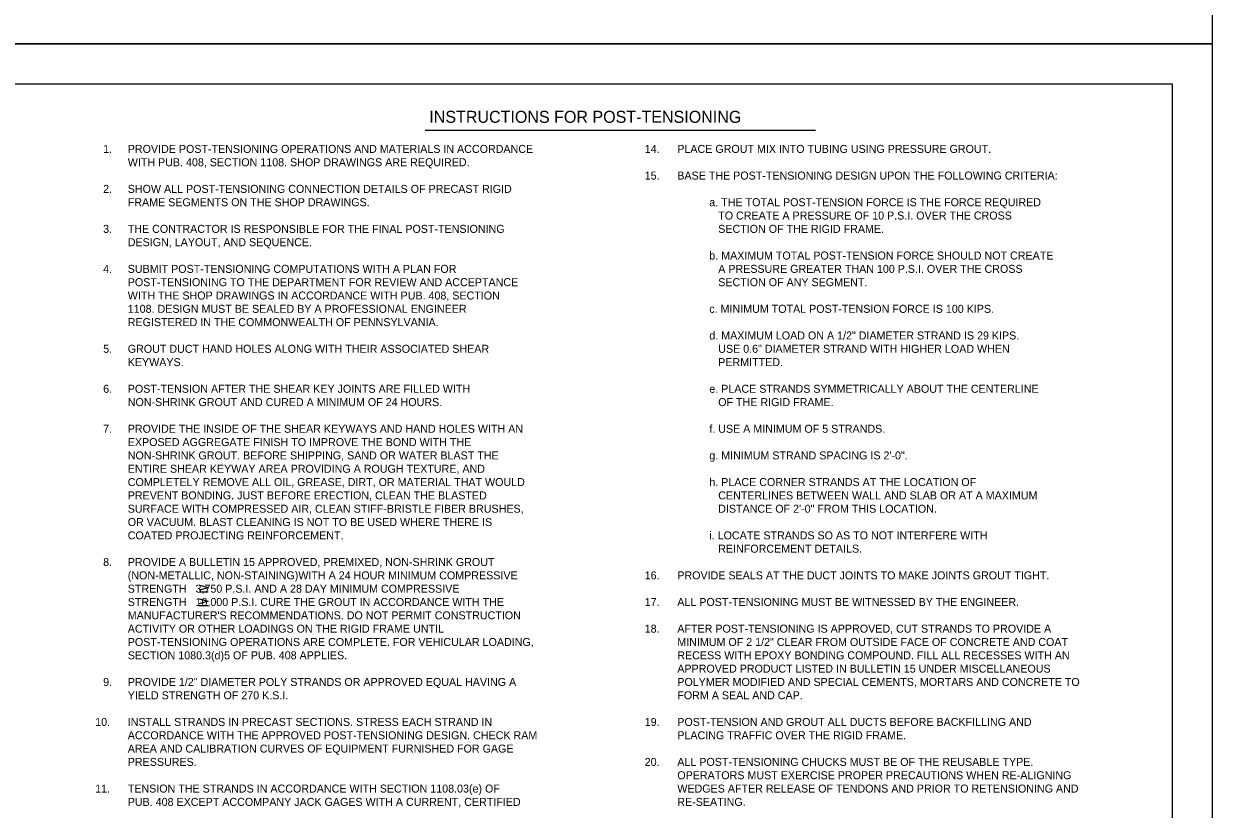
# Model space of a CAD drawing. Extents: x 641328 to 643024, y 298283 to 300065.
# Drawn here: x 642563.8 to 643009.5, y 299184.1 to 299478.8 of the extents above; entities that cross this region are included whole.
import ezdxf

# ---------------------------------------------------------------- set-up
doc = ezdxf.new("R2010")
doc.units = 0
doc.layers.add('2', color=7, linetype='Continuous')
doc.layers.add('PLT-BNDY', color=7, linetype='Continuous')

msp = doc.modelspace()

# ---------------------------------------------------------------- linework, layer by layer
at = {"layer": '2'}
for p, q in [((642208.51, 299456.3), (642994.5, 299456.3)), ((642994.5, 299456.3), (642994.5, 298892.3)), ((642714.31, 299438.86), (642860.76, 299438.86)), ((642629.74, 299268.18), (642633.11, 299267.31)), ((642629.6, 299265.61), (642632.97, 299265.61)), ((642629.74, 299266.43), (642633.11, 299267.31)), ((642629.44, 299260.5), (642632.82, 299260.5)), ((642629.58, 299263.07), (642632.96, 299262.2)), ((642629.58, 299261.32), (642632.96, 299262.2))]:
    msp.add_line(p, q, dxfattribs=at)
at = {"layer": 'PLT-BNDY'}
for points in [[(642168.51, 300065.3), (643009.51, 300065.3), (643009.51, 299471.3), (642168.51, 299471.3)], [(642168.51, 299471.3), (643009.51, 299471.3), (643009.51, 298877.3), (642168.51, 298877.3)]]:
    msp.add_lwpolyline(points, close=True, dxfattribs=at)

# ---------------------------------------------------------------- texts
at = {"layer": '2'}
for s, height, p in [('INSTRUCTIONS FOR POST-TENSIONING', 4.5, (642715.91, 299441.63)), ('1.', 3, (642593.61, 299430.34)), ('PROVIDE POST-TENSIONING OPERATIONS AND MATERIALS IN ACCORDANCE ', 3, (642602.83, 299430.34)), ('14.', 3, (642796.69, 299430.34)), ('PLACE GROUT MIX INTO TUBING USING PRESSURE GROUT. ', 3, (642808.91, 299430.34)), ('WITH PUB. 408, SECTION 1108. SHOP DRAWINGS ARE REQUIRED.', 3, (642602.83, 299425.34)), ('15.', 3, (642796.69, 299420.34)), ('BASE THE POST-TENSIONING DESIGN UPON THE FOLLOWING CRITERIA:', 3, (642808.91, 299420.34)), ('2.', 3, (642593.61, 299415.34)), ('SHOW ALL POST-TENSIONING CONNECTION DETAILS OF PRECAST RIGID ', 3, (642602.83, 299415.34)), ('FRAME SEGMENTS ON THE SHOP DRAWINGS.  ', 3, (642602.83, 299410.34)), ('a. THE TOTAL POST-TENSION FORCE IS THE FORCE REQUIRED ', 3, (642820.91, 299410.34)), ('   TO CREATE A PRESSURE OF 10 P.S.I. OVER THE CROSS ', 3, (642820.91, 299405.34)), ('3.', 3, (642593.61, 299400.34)), ('THE CONTRACTOR IS RESPONSIBLE FOR THE FINAL POST-TENSIONING ', 3, (642602.83, 299400.34)), ('   SECTION OF THE RIGID FRAME. ', 3, (642820.91, 299400.34)), ('DESIGN, LAYOUT, AND SEQUENCE.  ', 3, (642602.83, 299395.34)), ('b. MAXIMUM TOTAL POST-TENSION FORCE SHOULD NOT CREATE', 3, (642820.91, 299390.34)), ('4.', 3, (642593.61, 299385.34)), ('SUBMIT POST-TENSIONING COMPUTATIONS WITH A PLAN FOR ', 3, (642602.83, 299385.34)), ('   A PRESSURE GREATER THAN 100 P.S.I. OVER THE CROSS ', 3, (642820.91, 299385.34)), ('POST-TENSIONING TO THE DEPARTMENT FOR REVIEW AND ACCEPTANCE ', 3, (642602.83, 299380.34)), ('   SECTION OF ANY SEGMENT. ', 3, (642820.91, 299380.34)), ('WITH THE SHOP DRAWINGS IN ACCORDANCE WITH PUB. 408, SECTION ', 3, (642602.83, 299375.34)), ('1108. DESIGN MUST BE SEALED BY A PROFESSIONAL ENGINEER ', 3, (642602.83, 299370.34)), ('c. MINIMUM TOTAL POST-TENSION FORCE IS 100 KIPS.', 3, (642820.91, 299370.34)), ('REGISTERED IN THE COMMONWEALTH OF PENNSYLVANIA.', 3, (642602.83, 299365.34)), ('d. MAXIMUM LOAD ON A 1/2" DIAMETER STRAND IS 29 KIPS.', 3, (642820.91, 299360.34)), ('5.', 3, (642593.61, 299355.34)), ('GROUT DUCT HAND HOLES ALONG WITH THEIR ASSOCIATED SHEAR ', 3, (642602.83, 299355.34)), ('   USE 0.6" DIAMETER STRAND WITH HIGHER LOAD WHEN ', 3, (642820.91, 299355.34)), ('KEYWAYS.', 3, (642602.83, 299350.34)), ('   PERMITTED. ', 3, (642820.91, 299350.34)), ('6.', 3, (642593.61, 299340.34)), ('POST-TENSION AFTER THE SHEAR KEY JOINTS ARE FILLED WITH ', 3, (642602.83, 299340.34)), ('e. PLACE STRANDS SYMMETRICALLY ABOUT THE CENTERLINE ', 3, (642820.91, 299340.34)), ('NON-SHRINK GROUT AND CURED A MINIMUM OF 24 HOURS.', 3, (642602.83, 299335.34)), ('   OF THE RIGID FRAME.', 3, (642820.91, 299335.34)), ('7.', 3, (642593.61, 299325.34)), ('PROVIDE THE INSIDE OF THE SHEAR KEYWAYS AND HAND HOLES WITH AN ', 3, (642602.83, 299325.34)), ('f. USE A MINIMUM OF 5 STRANDS.', 3, (642820.91, 299325.34)), ('EXPOSED AGGREGATE FINISH TO IMPROVE THE BOND WITH THE ', 3, (642602.83, 299320.34)), ('NON-SHRINK GROUT. BEFORE SHIPPING, SAND OR WATER BLAST THE ', 3, (642602.83, 299315.34)), ('g. MINIMUM STRAND SPACING IS 2\'-0".', 3, (642820.91, 299315.34)), ('ENTIRE SHEAR KEYWAY AREA PROVIDING A ROUGH TEXTURE, AND ', 3, (642602.83, 299310.34)), ('COMPLETELY REMOVE ALL OIL, GREASE, DIRT, OR MATERIAL THAT WOULD ', 3, (642602.83, 299305.34)), ('h. PLACE CORNER STRANDS AT THE LOCATION OF', 3, (642820.91, 299305.34)), ('PREVENT BONDING. JUST BEFORE ERECTION, CLEAN THE BLASTED ', 3, (642602.83, 299300.34)), ('   CENTERLINES BETWEEN WALL AND SLAB OR AT A MAXIMUM', 3, (642820.91, 299300.34)), ('SURFACE WITH COMPRESSED AIR, CLEAN STIFF-BRISTLE FIBER BRUSHES, ', 3, (642602.83, 299295.34)), ('   DISTANCE OF 2\'-0" FROM THIS LOCATION. ', 3, (642820.91, 299295.34)), ('OR VACUUM. BLAST CLEANING IS NOT TO BE USED WHERE THERE IS ', 3, (642602.83, 299290.34)), ('COATED PROJECTING REINFORCEMENT.', 3, (642602.83, 299285.34)), ('i. LOCATE STRANDS SO AS TO NOT INTERFERE WITH ', 3, (642820.91, 299285.34)), ('   REINFORCEMENT DETAILS.', 3, (642820.91, 299280.34)), ('8.', 3, (642593.61, 299275.34)), ('PROVIDE A BULLETIN 15 APPROVED, PREMIXED, NON-SHRINK GROUT ', 3, (642602.83, 299275.34)), ('(NON-METALLIC, NON-STAINING)WITH A 24 HOUR MINIMUM COMPRESSIVE ', 3, (642602.83, 299270.34)), ('16.', 3, (642796.69, 299270.34)), ('PROVIDE SEALS AT THE DUCT JOINTS TO MAKE JOINTS GROUT TIGHT. ', 3, (642808.91, 299270.34)), ('STRENGTH   3,750 P.S.I. AND A 28 DAY MINIMUM COMPRESSIVE ', 3, (642602.83, 299265.34)), ('STRENGTH   10,000 P.S.I. CURE THE GROUT IN ACCORDANCE WITH THE ', 3, (642602.83, 299260.34)), ('17.', 3, (642796.69, 299260.34)), ('ALL POST-TENSIONING MUST BE WITNESSED BY THE ENGINEER. ', 3, (642808.91, 299260.34)), ("MANUFACTURER'S RECOMMENDATIONS. DO NOT PERMIT CONSTRUCTION ", 3, (642602.83, 299255.34)), ('ACTIVITY OR OTHER LOADINGS ON THE RIGID FRAME UNTIL ', 3, (642602.83, 299250.34)), ('18.', 3, (642796.69, 299250.34)), ('AFTER POST-TENSIONING IS APPROVED, CUT STRANDS TO PROVIDE A ', 3, (642808.91, 299250.34)), ('POST-TENSIONING OPERATIONS ARE COMPLETE. FOR VEHICULAR LOADING, ', 3, (642602.83, 299245.34)), ('MINIMUM OF 2 1/2" CLEAR FROM OUTSIDE FACE OF CONCRETE AND COAT ', 3, (642808.91, 299245.34)), ('SECTION 1080.3(d)5 OF PUB. 408 APPLIES.', 3, (642602.83, 299240.34)), ('RECESS WITH EPOXY BONDING COMPOUND. FILL ALL RECESSES WITH AN ', 3, (642808.91, 299240.34)), ('APPROVED PRODUCT LISTED IN BULLETIN 15 UNDER MISCELLANEOUS ', 3, (642808.91, 299235.34)), ('9.', 3, (642593.61, 299230.34)), ('PROVIDE 1/2" DIAMETER POLY STRANDS OR APPROVED EQUAL HAVING A ', 3, (642602.83, 299230.34)), ('POLYMER MODIFIED AND SPECIAL CEMENTS, MORTARS AND CONCRETE TO ', 3, (642808.91, 299230.34)), ('YIELD STRENGTH OF 270 K.S.I.', 3, (642602.83, 299225.34)), ('FORM A SEAL AND CAP.', 3, (642808.91, 299225.34)), ('10.', 3, (642590.61, 299215.34)), ('INSTALL STRANDS IN PRECAST SECTIONS. STRESS EACH STRAND IN ', 3, (642602.83, 299215.34)), ('19.', 3, (642796.69, 299215.34)), ('POST-TENSION AND GROUT ALL DUCTS BEFORE BACKFILLING AND ', 3, (642808.91, 299215.34)), ('ACCORDANCE WITH THE APPROVED POST-TENSIONING DESIGN. CHECK RAM ', 3, (642602.83, 299210.34)), ('PLACING TRAFFIC OVER THE RIGID FRAME.  ', 3, (642808.91, 299210.34)), ('AREA AND CALIBRATION CURVES OF EQUIPMENT FURNISHED FOR GAGE ', 3, (642602.83, 299205.34)), ('PRESSURES.', 3, (642602.83, 299200.34)), ('20.', 3, (642796.69, 299200.34)), ('ALL POST-TENSIONING CHUCKS MUST BE OF THE REUSABLE TYPE. ', 3, (642808.91, 299200.34)), ('OPERATORS MUST EXERCISE PROPER PRECAUTIONS WHEN RE-ALIGNING ', 3, (642808.91, 299195.34)), ('11.', 3, (642590.61, 299190.34)), ('TENSION THE STRANDS IN ACCORDANCE WITH SECTION 1108.03(e) OF ', 3, (642602.83, 299190.34)), ('WEDGES AFTER RELEASE OF TENDONS AND PRIOR TO RETENSIONING AND ', 3, (642808.91, 299190.34)), ('PUB. 408 EXCEPT ACCOMPANY JACK GAGES WITH A CURRENT, CERTIFIED ', 3, (642602.83, 299185.34)), ('RE-SEATING. ', 3, (642808.91, 299185.34))]:
    msp.add_text(s, height=height, dxfattribs=at).set_placement(p)

doc.saveas('drawing.dxf')
